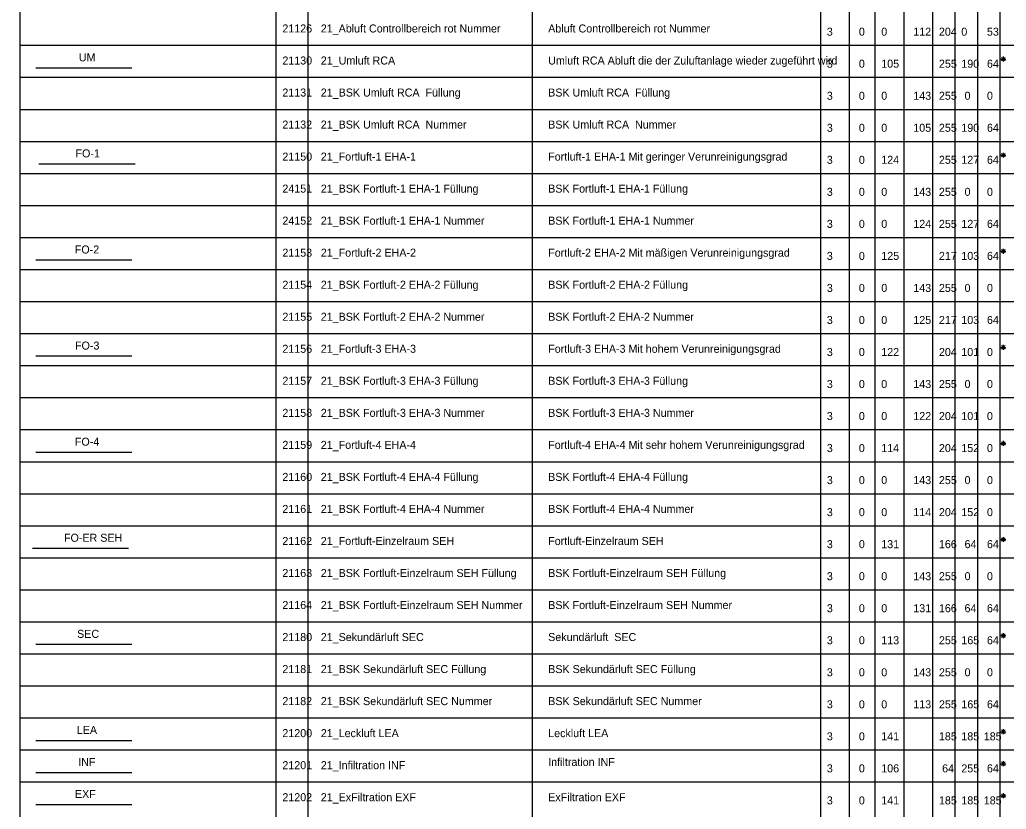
# Model space of a CAD drawing. Extents: x -12.9 to 27.6, y -77.8 to 7.2.
# Drawn here: x 0 to 15.4, y -47.43 to -35.1 of the extents above; entities that cross this region are included whole.
import ezdxf

# ---------------------------------------------------------------- set-up
doc = ezdxf.new("R2010")
doc.units = 0
for name, color, linetype in [('21_ExFiltration EXF', 7, 'Continuous'), ('21_Fortluft-1 EHA-1', 7, 'Continuous'), ('21_Fortluft-2 EHA-2', 7, 'Continuous'), ('21_Fortluft-3 EHA-3', 7, 'Continuous'), ('21_Fortluft-4 EHA-4', 7, 'Continuous'), ('21_Fortluft-Einezelraum SEH', 7, 'Continuous'), ('21_Infiltration INF', 7, 'Continuous'), ('21_Leckluft LEA', 7, 'Continuous'), ('21_Sekundärluft SEC', 7, 'Continuous'), ('21_Umluft RCA', 7, 'Continuous'), ('Default', 7, 'Continuous')]:
    doc.layers.add(name, color=color, linetype=linetype)

msp = doc.modelspace()

# ---------------------------------------------------------------- linework, layer by layer
at = {"layer": '21_ExFiltration EXF'}
msp.add_line((0.25, -47.35), (1.75, -47.35), dxfattribs=at)
at = {"layer": '21_Fortluft-1 EHA-1'}
msp.add_line((0.3, -37.35), (1.8, -37.35), dxfattribs=at)
at = {"layer": '21_Fortluft-2 EHA-2'}
msp.add_line((0.25, -38.85), (1.75, -38.85), dxfattribs=at)
at = {"layer": '21_Fortluft-3 EHA-3'}
msp.add_line((0.25, -40.35), (1.75, -40.35), dxfattribs=at)
at = {"layer": '21_Fortluft-4 EHA-4'}
msp.add_line((0.25, -41.85), (1.75, -41.85), dxfattribs=at)
at = {"layer": '21_Fortluft-Einezelraum SEH'}
msp.add_line((0.2, -43.35), (1.7, -43.35), dxfattribs=at)
at = {"layer": '21_Infiltration INF'}
msp.add_line((0.25, -46.85), (1.75, -46.85), dxfattribs=at)
at = {"layer": '21_Leckluft LEA'}
msp.add_line((0.25, -46.35), (1.75, -46.35), dxfattribs=at)
at = {"layer": '21_Sekundärluft SEC'}
msp.add_line((0.25, -44.85), (1.75, -44.85), dxfattribs=at)
at = {"layer": '21_Umluft RCA'}
msp.add_line((0.25, -35.85), (1.75, -35.85), dxfattribs=at)
at = {"layer": 'Default'}
for p, q in [((0, 0), (0, -73.5)), ((4, 0), (4, -73.5)), ((4.5, 0), (4.5, -73.5)), ((8, 0), (8, -73.5)), ((12.5, 0), (12.5, -73.5)), ((12.95, -0.35), (12.95, -59.5)), ((13.35, -0.35), (13.35, -59.5)), ((13.8, -0.35), (13.8, -59.5)), ((14.25, -0.35), (14.25, -59.5)), ((15.3, -0.35), (15.3, -59.5)), ((14.6, -0.75), (14.6, -59.5)), ((14.95, -0.75), (14.95, -59.5)), ((0, -35.5), (15.192, -35.5)), ((0, -35.5), (16.8, -35.5)), ((15.317, -35.715), (15.393, -35.715)), ((15.328, -35.688), (15.382, -35.742)), ((15.382, -35.688), (15.328, -35.742)), ((15.355, -35.677), (15.355, -35.753)), ((0, -36), (16.8, -36)), ((0, -36.5), (16.8, -36.5)), ((0, -37), (16.8, -37)), ((15.317, -37.215), (15.393, -37.215)), ((15.328, -37.188), (15.382, -37.242)), ((15.382, -37.188), (15.328, -37.242)), ((15.355, -37.177), (15.355, -37.253)), ((0, -37.5), (16.8, -37.5)), ((0, -38), (16.8, -38)), ((0, -38.5), (16.8, -38.5)), ((15.317, -38.715), (15.393, -38.715)), ((15.328, -38.688), (15.382, -38.742)), ((15.382, -38.688), (15.328, -38.742)), ((15.355, -38.677), (15.355, -38.753)), ((0, -39), (16.8, -39)), ((0, -39.5), (16.8, -39.5)), ((0, -40), (16.8, -40)), ((15.328, -40.188), (15.382, -40.242)), ((15.382, -40.188), (15.328, -40.242)), ((15.355, -40.177), (15.355, -40.253)), ((15.317, -40.215), (15.393, -40.215)), ((0, -40.5), (16.8, -40.5)), ((0, -41), (16.8, -41)), ((0, -41.5), (16.8, -41.5)), ((15.317, -41.715), (15.393, -41.715)), ((15.328, -41.688), (15.382, -41.742)), ((15.382, -41.688), (15.328, -41.742)), ((15.355, -41.677), (15.355, -41.753)), ((0, -42), (16.8, -42)), ((0, -42.5), (16.8, -42.5)), ((0, -43), (16.8, -43)), ((15.317, -43.215), (15.393, -43.215)), ((15.328, -43.188), (15.382, -43.242)), ((15.382, -43.188), (15.328, -43.242)), ((15.355, -43.177), (15.355, -43.253)), ((0, -43.5), (16.8, -43.5)), ((0, -44), (16.8, -44)), ((0, -44.5), (16.8, -44.5)), ((15.317, -44.715), (15.393, -44.715)), ((15.328, -44.688), (15.382, -44.742)), ((15.382, -44.688), (15.328, -44.742)), ((15.355, -44.677), (15.355, -44.753)), ((0, -45), (16.8, -45)), ((0, -45.5), (16.8, -45.5)), ((0, -46), (16.8, -46)), ((15.328, -46.188), (15.382, -46.242)), ((15.382, -46.188), (15.328, -46.242)), ((15.355, -46.177), (15.355, -46.253)), ((15.317, -46.215), (15.393, -46.215)), ((0, -46.5), (16.8, -46.5)), ((15.317, -46.715), (15.393, -46.715)), ((15.328, -46.688), (15.382, -46.742)), ((15.382, -46.688), (15.328, -46.742)), ((15.355, -46.677), (15.355, -46.753)), ((0, -47), (16.8, -47)), ((15.317, -47.215), (15.393, -47.215)), ((15.328, -47.188), (15.382, -47.242)), ((15.382, -47.188), (15.328, -47.242)), ((15.355, -47.177), (15.355, -47.253))]:
    msp.add_line(p, q, dxfattribs=at)

# ---------------------------------------------------------------- texts
at = {"layer": '21_ExFiltration EXF'}
msp.add_text('EXF ', height=0.125, dxfattribs=at).set_placement((0.862, -47.25))
at = {"layer": '21_Fortluft-1 EHA-1'}
msp.add_text('FO-1', height=0.125, dxfattribs=at).set_placement((0.871, -37.25))
at = {"layer": '21_Fortluft-2 EHA-2'}
msp.add_text('FO-2', height=0.125, dxfattribs=at).set_placement((0.86, -38.75))
at = {"layer": '21_Fortluft-3 EHA-3'}
msp.add_text('FO-3', height=0.125, dxfattribs=at).set_placement((0.863, -40.25))
at = {"layer": '21_Fortluft-4 EHA-4'}
msp.add_text('FO-4', height=0.125, dxfattribs=at).set_placement((0.861, -41.75))
at = {"layer": '21_Fortluft-Einezelraum SEH'}
msp.add_text('FO-ER SEH', height=0.125, dxfattribs=at).set_placement((0.691, -43.25))
at = {"layer": '21_Infiltration INF'}
msp.add_text('INF', height=0.125, dxfattribs=at).set_placement((0.913, -46.75))
at = {"layer": '21_Leckluft LEA'}
msp.add_text('LEA', height=0.125, dxfattribs=at).set_placement((0.891, -46.25))
at = {"layer": '21_Sekundärluft SEC'}
msp.add_text('SEC', height=0.125, dxfattribs=at).set_placement((0.896, -44.75))
at = {"layer": '21_Umluft RCA'}
msp.add_text('UM', height=0.125, dxfattribs=at).set_placement((0.923, -35.75))
at = {"layer": 'Default'}
for s, p in [('21126', (4.1, -35.3)), ('21_Abluft Controllbereich rot Nummer', (4.7, -35.3)), ('Abluft Controllbereich rot Nummer', (8.25, -35.3)), ('3', (12.6, -35.35)), ('0', (13.1, -35.35)), ('0', (13.45, -35.35)), ('112', (13.95, -35.35)), ('204', (14.35, -35.35)), ('0', (14.7, -35.35)), ('53', (15.1, -35.35)), ('21130', (4.1, -35.8)), ('21_Umluft RCA ', (4.7, -35.8)), ('Umluft RCA Abluft die der Zuluftanlage wieder zugeführt wird', (8.25, -35.8)), ('3', (12.6, -35.85)), ('0', (13.1, -35.85)), ('105', (13.45, -35.85)), ('255', (14.35, -35.85)), ('190', (14.7, -35.85)), ('64', (15.1, -35.85)), ('21131', (4.1, -36.3)), ('21_BSK Umluft RCA  Füllung', (4.7, -36.3)), ('BSK Umluft RCA  Füllung', (8.25, -36.3)), ('3', (12.6, -36.35)), ('0', (13.1, -36.35)), ('0', (13.45, -36.35)), ('143', (13.95, -36.35)), ('255', (14.35, -36.35)), ('0', (14.75, -36.35)), ('0', (15.1, -36.35)), ('21132', (4.1, -36.8)), ('21_BSK Umluft RCA  Nummer', (4.7, -36.8)), ('BSK Umluft RCA  Nummer', (8.25, -36.8)), ('3', (12.6, -36.85)), ('0', (13.1, -36.85)), ('0', (13.45, -36.85)), ('105', (13.95, -36.85)), ('255', (14.35, -36.85)), ('190', (14.7, -36.85)), ('64', (15.1, -36.85)), ('21150', (4.1, -37.3)), ('21_Fortluft-1 EHA-1', (4.7, -37.3)), ('Fortluft-1 EHA-1 Mit geringer Verunreinigungsgrad', (8.25, -37.3)), ('3', (12.6, -37.35)), ('0', (13.1, -37.35)), ('124', (13.45, -37.35)), ('255', (14.35, -37.35)), ('127', (14.7, -37.35)), ('64', (15.1, -37.35)), ('24151', (4.1, -37.8)), ('21_BSK Fortluft-1 EHA-1 Füllung', (4.7, -37.8)), ('BSK Fortluft-1 EHA-1 Füllung', (8.25, -37.8)), ('3', (12.6, -37.85)), ('0', (13.1, -37.85)), ('0', (13.45, -37.85)), ('143', (13.95, -37.85)), ('255', (14.35, -37.85)), ('0', (14.75, -37.85)), ('0', (15.1, -37.85)), ('24152', (4.1, -38.3)), ('21_BSK Fortluft-1 EHA-1 Nummer', (4.7, -38.3)), ('BSK Fortluft-1 EHA-1 Nummer', (8.25, -38.3)), ('3', (12.6, -38.35)), ('0', (13.1, -38.35)), ('0', (13.45, -38.35)), ('124', (13.95, -38.35)), ('255', (14.35, -38.35)), ('127', (14.7, -38.35)), ('64', (15.1, -38.35)), ('21153', (4.1, -38.8)), ('21_Fortluft-2 EHA-2', (4.7, -38.8)), ('Fortluft-2 EHA-2 Mit mäßigen Verunreinigungsgrad', (8.25, -38.8)), ('3', (12.6, -38.85)), ('0', (13.1, -38.85)), ('125', (13.45, -38.85)), ('217', (14.35, -38.85)), ('103', (14.7, -38.85)), ('64', (15.1, -38.85)), ('21154', (4.1, -39.3)), ('21_BSK Fortluft-2 EHA-2 Füllung', (4.7, -39.3)), ('BSK Fortluft-2 EHA-2 Füllung', (8.25, -39.3)), ('3', (12.6, -39.35)), ('0', (13.1, -39.35)), ('0', (13.45, -39.35)), ('143', (13.95, -39.35)), ('255', (14.35, -39.35)), ('0', (14.75, -39.35)), ('0', (15.1, -39.35)), ('21155', (4.1, -39.8)), ('21_BSK Fortluft-2 EHA-2 Nummer', (4.7, -39.8)), ('BSK Fortluft-2 EHA-2 Nummer', (8.25, -39.8)), ('3', (12.6, -39.85)), ('0', (13.1, -39.85)), ('0', (13.45, -39.85)), ('125', (13.95, -39.85)), ('217', (14.35, -39.85)), ('103', (14.7, -39.85)), ('64', (15.1, -39.85)), ('21156', (4.1, -40.3)), ('21_Fortluft-3 EHA-3', (4.7, -40.3)), ('Fortluft-3 EHA-3 Mit hohem Verunreinigungsgrad', (8.25, -40.3)), ('3', (12.6, -40.35)), ('0', (13.1, -40.35)), ('122', (13.45, -40.35)), ('204', (14.35, -40.35)), ('101', (14.7, -40.35)), ('0', (15.1, -40.35)), ('21157', (4.1, -40.8)), ('21_BSK Fortluft-3 EHA-3 Füllung', (4.7, -40.8)), ('BSK Fortluft-3 EHA-3 Füllung', (8.25, -40.8)), ('3', (12.6, -40.85)), ('0', (13.1, -40.85)), ('0', (13.45, -40.85)), ('143', (13.95, -40.85)), ('255', (14.35, -40.85)), ('0', (14.75, -40.85)), ('0', (15.1, -40.85)), ('21158', (4.1, -41.3)), ('21_BSK Fortluft-3 EHA-3 Nummer', (4.7, -41.3)), ('BSK Fortluft-3 EHA-3 Nummer', (8.25, -41.3)), ('3', (12.6, -41.35)), ('0', (13.1, -41.35)), ('0', (13.45, -41.35)), ('122', (13.95, -41.35)), ('204', (14.35, -41.35)), ('101', (14.7, -41.35)), ('0', (15.1, -41.35)), ('21159', (4.1, -41.8)), ('21_Fortluft-4 EHA-4', (4.7, -41.8)), ('Fortluft-4 EHA-4 Mit sehr hohem Verunreinigungsgrad', (8.25, -41.8)), ('3', (12.6, -41.85)), ('0', (13.1, -41.85)), ('114', (13.45, -41.85)), ('204', (14.35, -41.85)), ('152', (14.7, -41.85)), ('0', (15.1, -41.85)), ('21160', (4.1, -42.3)), ('21_BSK Fortluft-4 EHA-4 Füllung', (4.7, -42.3)), ('BSK Fortluft-4 EHA-4 Füllung', (8.25, -42.3)), ('3', (12.6, -42.35)), ('0', (13.1, -42.35)), ('0', (13.45, -42.35)), ('143', (13.95, -42.35)), ('255', (14.35, -42.35)), ('0', (14.75, -42.35)), ('0', (15.1, -42.35)), ('21161', (4.1, -42.8)), ('21_BSK Fortluft-4 EHA-4 Nummer', (4.7, -42.8)), ('BSK Fortluft-4 EHA-4 Nummer', (8.25, -42.8)), ('3', (12.6, -42.85)), ('0', (13.1, -42.85)), ('0', (13.45, -42.85)), ('114', (13.95, -42.85)), ('204', (14.35, -42.85)), ('204', (14.35, -42.85)), ('152', (14.7, -42.85)), ('152', (14.7, -42.85)), ('0', (15.1, -42.85)), ('0', (15.1, -42.85)), ('21162', (4.1, -43.3)), ('21_Fortluft-Einzelraum SEH', (4.7, -43.3)), ('Fortluft-Einzelraum SEH', (8.25, -43.3)), ('3', (12.6, -43.35)), ('0', (13.1, -43.35)), ('131', (13.45, -43.35)), ('166', (14.35, -43.35)), ('64', (14.75, -43.35)), ('64', (15.1, -43.35)), ('21163', (4.1, -43.8)), ('21_BSK Fortluft-Einzelraum SEH Füllung', (4.7, -43.8)), ('BSK Fortluft-Einzelraum SEH Füllung', (8.25, -43.8)), ('3', (12.6, -43.85)), ('0', (13.1, -43.85)), ('0', (13.45, -43.85)), ('143', (13.95, -43.85)), ('255', (14.35, -43.85)), ('0', (14.75, -43.85)), ('0', (15.1, -43.85)), ('21164', (4.1, -44.3)), ('21_BSK Fortluft-Einzelraum SEH Nummer', (4.7, -44.3)), ('BSK Fortluft-Einzelraum SEH Nummer', (8.25, -44.3)), ('3', (12.6, -44.35)), ('0', (13.1, -44.35)), ('0', (13.45, -44.35)), ('131', (13.95, -44.35)), ('166', (14.35, -44.35)), ('64', (14.75, -44.35)), ('64', (15.1, -44.35)), ('21180', (4.1, -44.8)), ('21_Sekundärluft SEC ', (4.7, -44.8)), ('Sekundärluft  SEC ', (8.25, -44.8)), ('3', (12.6, -44.85)), ('0', (13.1, -44.85)), ('113', (13.45, -44.85)), ('255', (14.35, -44.85)), ('165', (14.7, -44.85)), ('64', (15.1, -44.85)), ('21181', (4.1, -45.3)), ('21_BSK Sekundärluft SEC Füllung', (4.7, -45.3)), ('BSK Sekundärluft SEC Füllung', (8.25, -45.3)), ('3', (12.6, -45.35)), ('0', (13.1, -45.35)), ('0', (13.45, -45.35)), ('143', (13.95, -45.35)), ('255', (14.35, -45.35)), ('0', (14.75, -45.35)), ('0', (15.1, -45.35)), ('21182', (4.1, -45.8)), ('21_BSK Sekundärluft SEC Nummer', (4.7, -45.8)), ('BSK Sekundärluft SEC Nummer', (8.25, -45.8)), ('3', (12.6, -45.85)), ('0', (13.1, -45.85)), ('0', (13.45, -45.85)), ('113', (13.95, -45.85)), ('255', (14.35, -45.85)), ('165', (14.7, -45.85)), ('64', (15.1, -45.85)), ('21200', (4.1, -46.3)), ('21_Leckluft LEA ', (4.7, -46.3)), ('Leckluft LEA ', (8.25, -46.3)), ('3', (12.6, -46.35)), ('0', (13.1, -46.35)), ('141', (13.45, -46.35)), ('185', (14.35, -46.35)), ('185', (14.7, -46.35)), ('185', (15.05, -46.35)), ('Infiltration INF ', (8.25, -46.75)), ('21201', (4.1, -46.8)), ('21_Infiltration INF ', (4.7, -46.8)), ('3', (12.6, -46.85)), ('0', (13.1, -46.85)), ('106', (13.45, -46.85)), ('64', (14.4, -46.85)), ('255', (14.7, -46.85)), ('64', (15.1, -46.85)), ('21202', (4.1, -47.3)), ('21_ExFiltration EXF ', (4.7, -47.3)), ('ExFiltration EXF ', (8.25, -47.3)), ('3', (12.6, -47.35)), ('0', (13.1, -47.35)), ('141', (13.45, -47.35)), ('185', (14.35, -47.35)), ('185', (14.7, -47.35)), ('185', (15.05, -47.35))]:
    msp.add_text(s, height=0.125, dxfattribs=at).set_placement(p)

doc.saveas('drawing.dxf')
